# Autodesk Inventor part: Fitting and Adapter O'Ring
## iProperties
Category: Hydraulics
Title: Fitting and Adapter O'Ring
Author: QBZ
Comments: 90 Durometer Buna-N Nitrile Rubber
Shininess: 41.0
PropertySet Name: _Private Model Information
Created: 2001-03
Part Number: FF9446-214
Material: Nitrile Rubber
Catalog Web Link: http://www.aeroquip.com
Description: Flange O-Ring -12
Document SubType Name: Modeling
Designer: QBZ
Control State: 0
Master: False
Checked Out: False
PropertySet Name: Design Tracking Control
Density: 1.15
Volumn: 0.6427949696235634
Area: 8.435629522618944
PropertySet Name: Model Information
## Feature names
1. Revolution1
